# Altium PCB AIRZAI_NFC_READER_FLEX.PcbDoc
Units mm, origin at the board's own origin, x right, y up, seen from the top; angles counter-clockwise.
Board outline 158.45 x 20.7 mm, 2 copper layers (Top Layer, Bottom Layer); 35 components, 44 nets, 105 pads, 9 vias.
Unrouted connection lines stored in the file: 71.
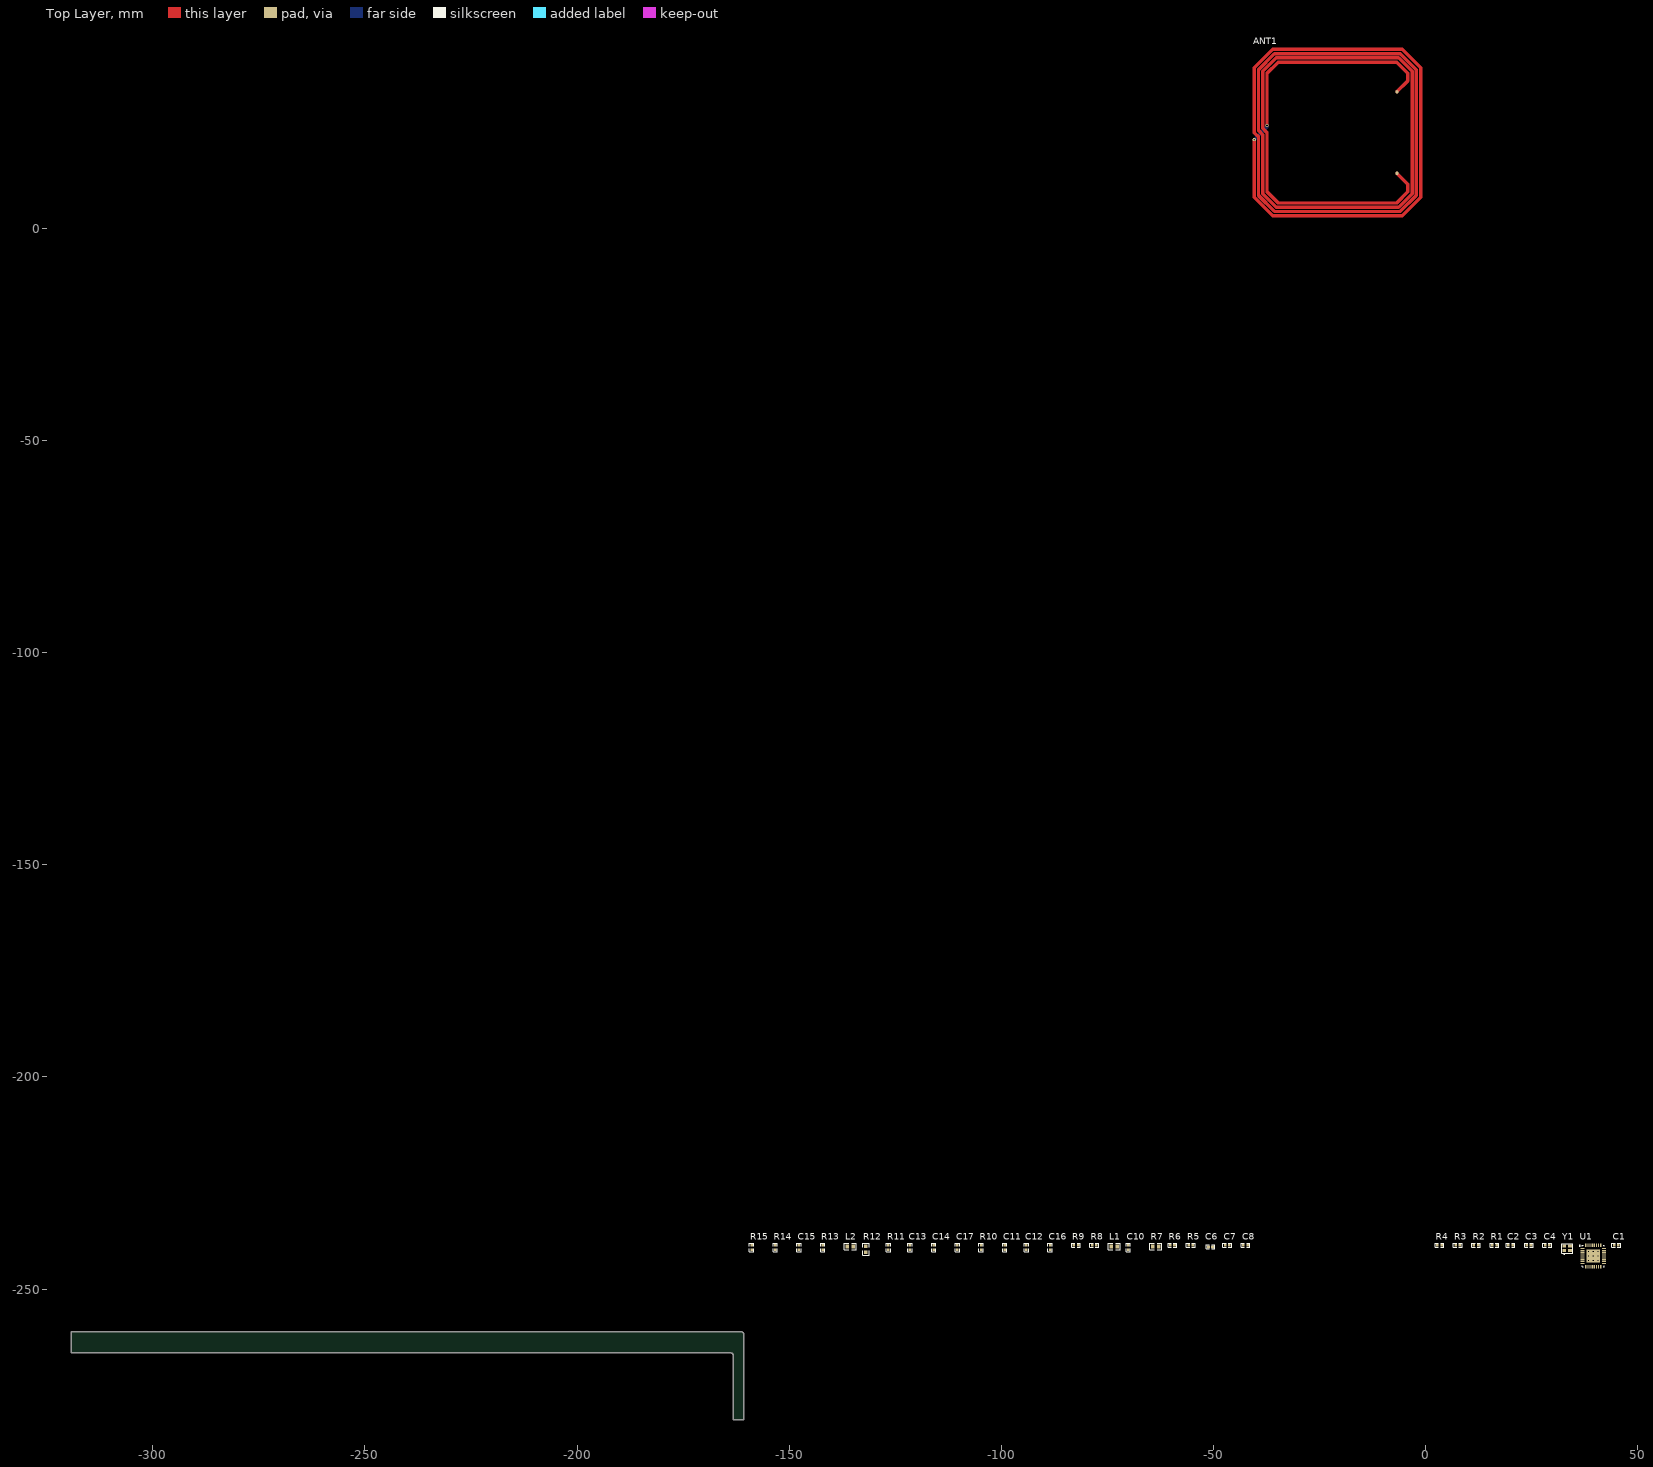
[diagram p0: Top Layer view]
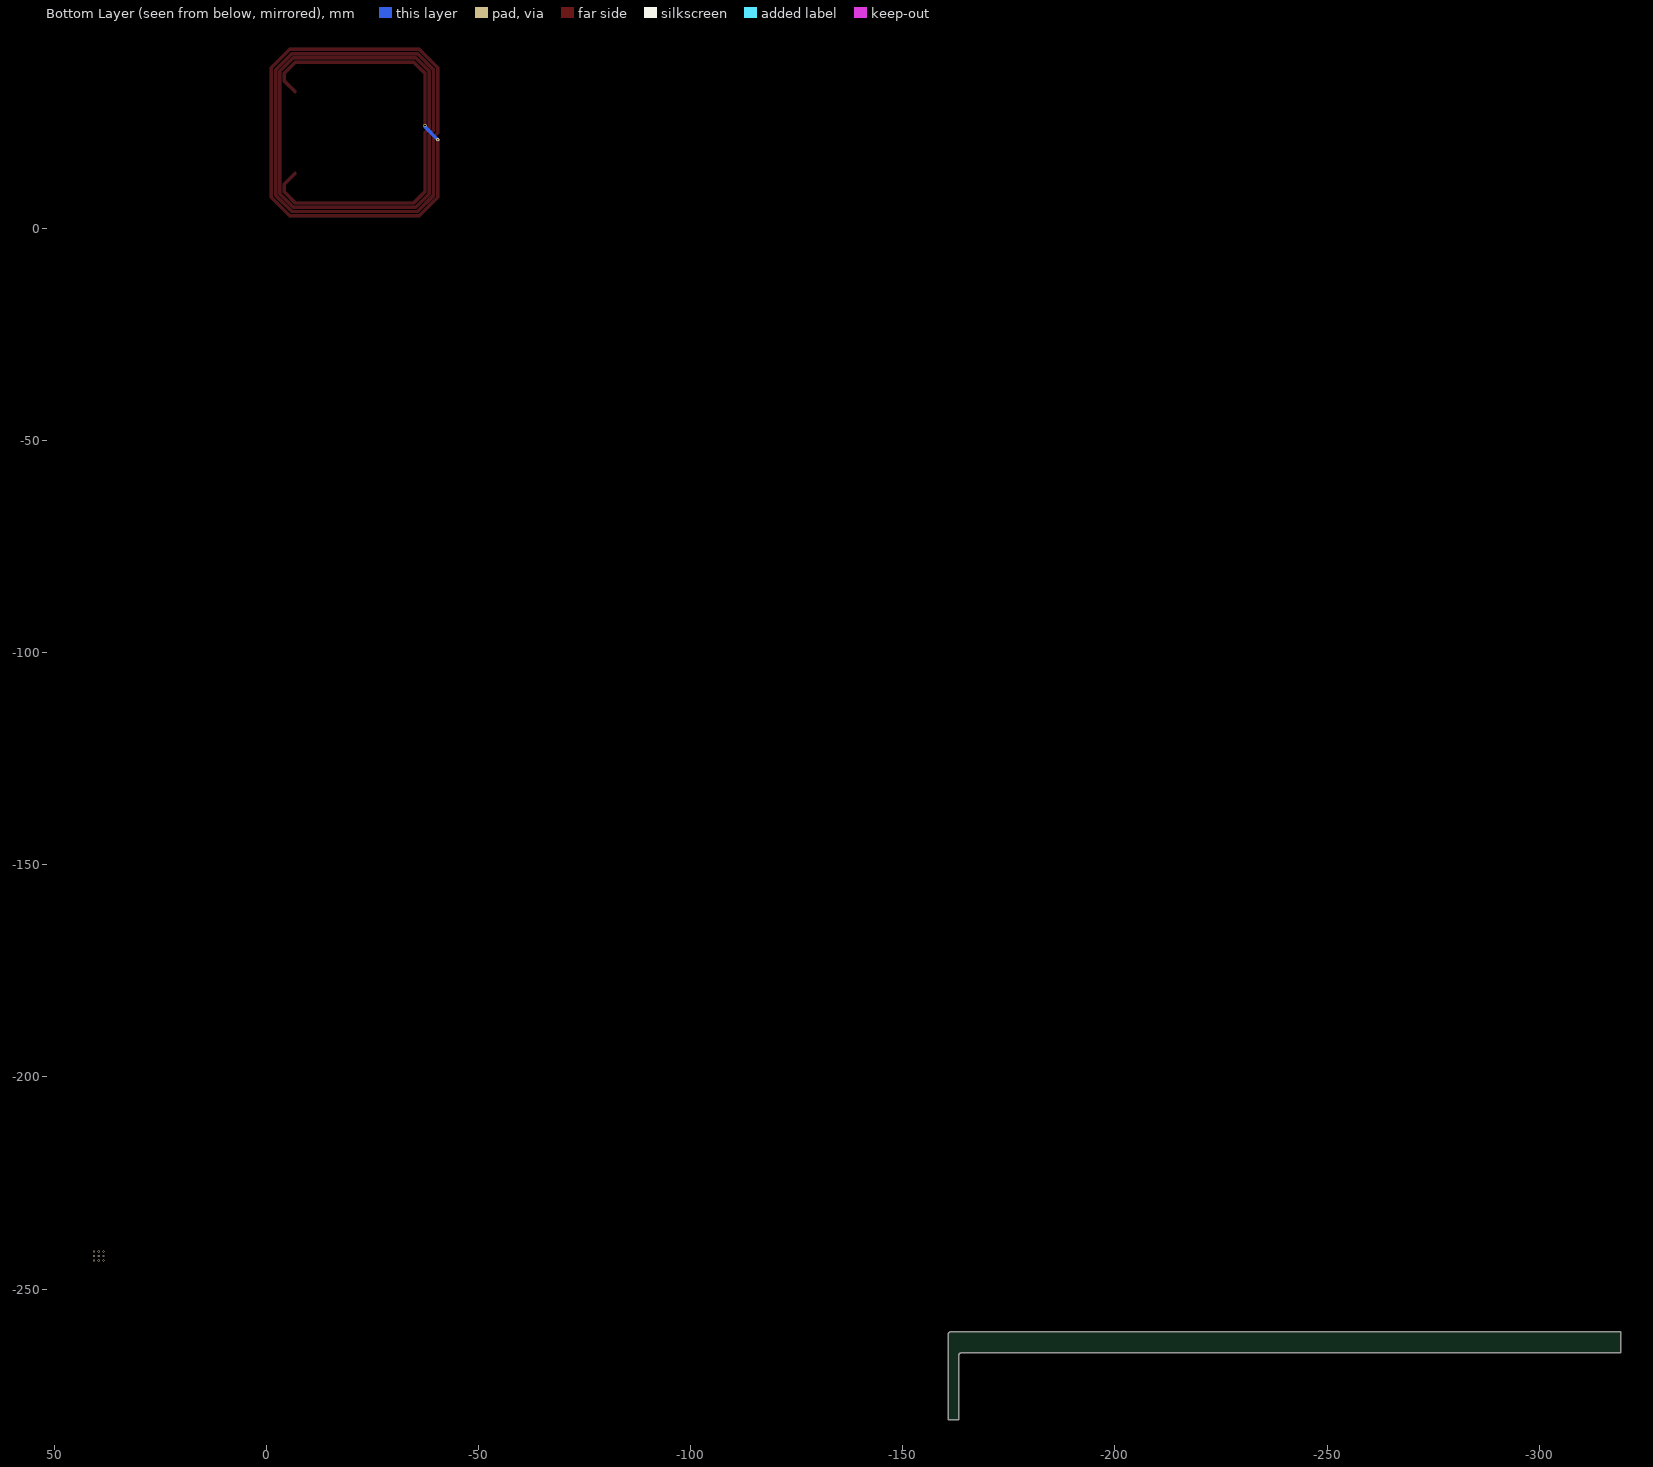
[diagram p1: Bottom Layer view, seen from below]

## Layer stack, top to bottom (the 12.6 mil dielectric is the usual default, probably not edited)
Top Solder: solder mask 0.0102, Solder Resist, Dk 3.5
Top Layer: signal copper 0.0356
Dielectric 1: dielectric 0.32, FR-4, Dk 4.8
Bottom Layer: signal copper 0.0356
Bottom Solder: solder mask 0.0102, Solder Resist, Dk 3.5

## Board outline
-319.17,-265.057 -319.17,-260.057 -161.356,-260.057 cw(c-161.356,-260.693) -160.72,-260.693 -160.72,-280.757 -163.22,-280.757 -163.22,-265.557 ccw(c-163.72,-265.557) -163.72,-265.057
board region "Layer Stack Region 1": -160.72,-274.15 -160.72,-280.757 -163.22,-280.757 -163.22,-274.15
board region "Layer Stack Region 1": -163.22,-273.337 -163.22,-265.557 -163.229,-265.459 -163.304,-265.279 -163.442,-265.141 -163.622,-265.066 -163.72,-265.057 -319.17,-265.057 -319.17,-260.057 -161.356,-260.057 -161.229,-260.057 -160.995,-260.153 -160.816,-260.332 -160.72,-260.566 -160.72,-260.693 -160.72,-273.337
board region "Layer Stack Region 2": -163.22,-274.15 -163.22,-273.337 -160.72,-273.337 -160.72,-274.15

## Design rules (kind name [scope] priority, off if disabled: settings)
Clearance Clearance_polygon_5V [OnLayer('Keep-Out Layer') vs (InNet('+5V') AND InPolygon)] p1: gap=0.254 ignorepadtopadclearanceinfootprint=FALSE
Clearance Clearance_POLYGON_KEEPOUT [(OnLayer('Keep-Out Layer')) vs (InNet('GND') AND InPolygon)] p2: gap=0.254 ignorepadtopadclearanceinfootprint=FALSE
Clearance [All] p3: gap=0.152 ignorepadtopadclearanceinfootprint=FALSE
MinimumSolderMaskSliver [All] p1: minsoldermaskwidth=0.025
PolygonConnect [All] p1: connectstyle=Direct reliefconductorwidth=0.254 reliefentries=4 polygonreliefangle="90 Angle" airgapwidth=0.254
RoomDefinition AIRZAI_NFC_READER_FLEX [InComponentClass('AIRZAI_NFC_READER_FLEX')] p1: confinementstyle=ConfineIn formatcopy=TRUE lockcomponents=FALSE outline -425.447,-395.268 -53.083,-395.268 -53.083,-151.428 -425.447,-151.428
RoutingVias [All] p1: holewidth=0.711 width=1.27 viastyle="Through Hole" minholewidth=0.203 minwidth=0.406 maxholewidth=0.711 maxwidth=1.27
SilkToSilkClearance [All] p1: silktosilkclearance=0.025
SilkToSolderMaskClearance [IsPad] p1: minsilkscreentomaskgap=0.051 clearancetoexposedcopper=TRUE
SolderMaskExpansion [All] p1: expansion=0.102
UnRoutedNet [All] p1: checkbadconnections=TRUE
Width [All] p1: maxlimit=2.54 minlimit=0.152 preferedwidth=0.254
26 further rules are at their usual default settings.

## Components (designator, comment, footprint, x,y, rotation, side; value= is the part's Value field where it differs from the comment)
ANT1 "NFC_ANT" ANTENNA-NFC-40MMX40MM -20.79,22.568 r270 top
C1 "12pF" 0402CAP 44.936,-239.693 r0 top
C2 "0.1µF" 0402CAP 20.018,-239.693 r0 top
C3 "0.1µF" 0402CAP 24.336,-239.693 r0 top
C4 "0.1µF" 0402CAP 28.654,-239.693 r0 top
C6 "1uF" CAPC0402(1005)60_M -50.721,-240.049 r0 top
C7 "0.1µF" 0402CAP -46.758,-239.693 r0 top
C8 "0.1µF" 0402CAP -42.44,-239.693 r0 top
C10 "18pF" 0402CAP -70.101,-240.201 r90 top
C11 "220pF" 0402CAP -99.184,-240.201 r90 top
C12 "47pF" 0402CAP -94.104,-240.201 r90 top
C13 "220pF" 0402CAP -121.536,-240.201 r90 top
C14 "47pF" 0402CAP -115.948,-240.201 r90 top
C15 "18pF" 0402CAP -147.698,-240.201 r90 top
C16 "DNP" 0402CAP -88.516,-240.201 r90 top
C17 "DNP" 0402CAP -110.36,-240.201 r90 top
L1 "560nH" 0603CAP -73.403,-239.947 r0 top
L2 "560mH" 0603CAP -135.633,-239.947 r0 top
R1 "0R" 0402 16.208,-239.693 r0 top
R2 "10K" 0402 11.89,-239.693 r0 top
R3 "10K" 0402 7.572,-239.693 r0 top
R4 "10K" 0402 3.254,-239.693 r0 top
R5 "1K" 0402 -55.369,-239.693 r0 top
R6 "2.7K" 0402 -59.687,-239.693 r0 top
R7 "3.3" 0603 -63.624,-239.947 r0 top
R8 "10K" 0402 -78.102,-239.693 r0 top
R9 "10K" 0402 -82.42,-239.693 r0 top
R10 "0R" 0402 -104.772,-240.201 r90 top
R11 "0R" 0402 -126.616,-240.201 r90 top
R12 "3.3" 0603 -131.95,-240.582 r90 top
R13 "10K" 0402 -142.11,-240.201 r90 top
R14 "0R" 0402 -153.286,-240.201 r90 top
R15 "0R" 0402 -158.874,-240.201 r90 top
U1 "MFRC52201HN1,157" VFQFN-32-MFRC52202HN1,157 39.5,-242.208 r0 top
Y1 "27.12MHz" XTAL_2016 33.353,-240.404 r0 top

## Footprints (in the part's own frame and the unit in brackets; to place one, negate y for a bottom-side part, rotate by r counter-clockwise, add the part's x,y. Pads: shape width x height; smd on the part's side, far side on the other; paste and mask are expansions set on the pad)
0402 [mm] "Chip Resistor, Body 1.1x0.5mm, IPC High Density"
  rect 0.6x0.6 smd: 1(-0.5,0) 2(0.5,0)
  silkscreen extent -1.02,-0.51 1.02,0.51, body extent -0.5,-0.25 0.5,0.25, height 0.27
0402CAP [mm] "Chip Capacitor, Body 1.1x0.5mm, IPC High Density"
  rect 0.6x0.6 smd: 1(-0.5,0) 2(0.5,0)
  silkscreen extent -1.02,-0.51 1.02,0.51, body extent -0.5,-0.3 0.5,0.3, height 0.19
0603 [mm] "Chip Resistor, Body 1.6x0.8mm, IPC High Density"
  rect 0.8x0.9 smd: 1(-0.7,0) 2(0.7,0)
  silkscreen extent -1.4,-0.76 1.4,0.76, body extent -0.8,-0.41 0.8,0.4, height 0.37
0603CAP [mm] "Chip Capacitor, Body 1.6x0.8mm, IPC High Density"
  rect 0.8x0.9 smd: 1(-0.7,0) 2(0.7,0)
  silkscreen extent -1.4,-0.76 1.4,0.76, body extent -0.8,-0.4 0.8,0.4, height 0.29
ANTENNA-NFC-40MMX40MM [mil] "ANTENNA-ID2+10P-01"
  round 31.5 smd: 1(-377.5,552.5) 2(377.5,552.5)
  round 30 hole 15: 1(-65,-653.54) 2(65,-771.65)
  Top Layer lines w31.5: -601.26,-771.65 -771.65,-601.26 -771.65,601.26 -601.26,771.65 601.26,771.65 771.65,601.26 771.65,-601.26 601.26,-771.65 65,-771.65 ; -601.26,-771.65 0,-771.65 39.37,-732.28 584.17,-732.28 732.28,-584.17 732.28,584.17 584.17,732.28 -584.17,732.28 -732.28,584.17 -732.28,-584.17 ; -65,-653.54 -550,-653.54 -653.54,-550 -653.54,550 -550,653.54 -478.54,653.54 -377.5,552.5 ; -732.28,-584.17 -584.17,-732.28 -19.37,-732.28 20,-692.91 567.09,-692.91 692.91,-567.09 692.91,567.09 567.09,692.91 -567.09,692.91 -692.91,567.09 -692.91,-567.09 -567.09,-692.91 -39.37,-692.91 0,-653.54 550,-653.54 653.54,-550 653.54,550 550,653.54 478.54,653.54 377.5,552.5
  Bottom Layer lines w31.5: 65,-771.65 -53.11,-653.54 -65,-653.54
CAPC0402(1005)60_M [mm] "Chip Capacitor, Body 1.0x0.5mm, Height 0.6mm, IPC Low Density"
  rect 0.72x0.72 smd: 1(-0.5,0) 2(0.5,0)
  silkscreen extent -1.02,-0.51 1.02,0.51, body extent -0.55,-0.3 0.55,0.3, height 0.6
VFQFN-32-MFRC52202HN1,157 [mm]
  rect 0.9x0.31 smd: 1(-2.529,1.75) 2(-2.529,1.25) 3(-2.529,0.75) 4(-2.529,0.25) 5(-2.529,-0.25) 6(-2.529,-0.75) 7(-2.529,-1.25) 8(-2.529,-1.75) 17(2.529,-1.75) 18(2.529,-1.25) 19(2.529,-0.75) 20(2.529,-0.25) 21(2.529,0.25) 22(2.529,0.75) 23(2.529,1.25) 24(2.529,1.75)
  rect 0.31x0.9 smd: 9(-1.75,-2.529) 10(-1.25,-2.529) 11(-0.75,-2.529) 12(-0.25,-2.529) 13(0.25,-2.529) 14(0.75,-2.529) 15(1.25,-2.529) 16(1.75,-2.529) 25(1.75,2.529) 26(1.25,2.529) 27(0.75,2.529) 28(0.25,2.529) 29(-0.25,2.529) 30(-0.75,2.529) 31(-1.25,2.529) 32(-1.75,2.529)
  rect 3.1x3.1 smd: 33(0,0)
  silkscreen extent -3.32,-2.55 2.55,2.55, body extent -2.55,-2.55 2.55,2.55, height 1
XTAL_2016 [mm] "2.00mm x 1.60mm"
  rect 0.85x0.75 smd: 1(-0.675,-0.525) 2(0.675,-0.525) 3(0.675,0.525) 4(-0.675,0.525)
  silkscreen extent -1.32,-1.47 1.32,1.14, body extent -1,-0.81 1,0.79, height 0.65

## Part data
C1: library part CAP, "CAP CER 12PF 50V C0G/NP0 0402", Case/Package=0402, Case Code (Metric)=1005, Dielectric=C0G, Dielectric Material=Ceramic, Manufacturer=KEMET, Manufacturer Part Number=C0402C120J5GACTU, Max Operating Temperature=125°C, Min Operating Temperature=-55°C, Package Quantity=1, Supplier Part Number 1=399-1013-6-ND, Temperature Coefficient=30ppm/°C, Tolerance=5%, Voltage=50V
C2 C3 C4 C7 C8: library part C0402-100n, "Capacitor, X7R, ±10%", Case-EIA=0402, Case-Metric=1005, Manufacturer=TDK, Manufacturer Part Number=C1005X7R1C104K, Rated Voltage="16 V", Supplier Part Number 1=445-4952-2-ND, Tolerance=±20%
C6: library part CAP, "CAP 1uF 16V ±10% 0402 (1005 Metric) Thickness 0.6mm SMD", Case/Package=0402, Case Code (Metric)=1005, Dielectric=X5R, Manufacturer="Taiyo Yuden", Manufacturer Part Number=EMK105BJ105KV-F, Max Operating Temperature=85°C, Min Operating Temperature=-55°C, Package Quantity=1, Supplier Part Number 1=587-2477-6-ND, Tolerance=10%, Voltage Rating=16V
C10 C15: library part 56p, "CAP CER 18PF 50V NP0 0402", Case/Package=0402, Case Code (Metric)=1005, Dielectric=C0G, Manufacturer="Kyocera AVX", Manufacturer Part Number=04025U180FAT2A, Max Operating Temperature=125°C, Min Operating Temperature=-55°C, Package Quantity=10000, Supplier Part Number 1=478-10144-1-ND, Tolerance=1%, Voltage Rating=50V
C11 C13: library part 56p, "CAP CER 220PF 50V NPO 0402", Case/Package=0402, Case Code (Metric)=1005, Dielectric=C0G, Manufacturer=Yageo, Manufacturer Part Number=CC0402FRNPO9BN221, Max Operating Temperature=125°C, Min Operating Temperature=-55°C, Supplier Part Number 1=311-3730-1-ND, Tolerance=1%, Voltage Rating=50V
C12 C14: library part 56p, "CAP CER 47PF 50V C0G/NP0 0402", Dielectric=C0G, Manufacturer=Murata, Manufacturer Part Number=GJM1555C1H470FB01D, Supplier Part Number 1=490-16376-1-ND, Tolerance=1%, Voltage Rating (DC)=50V
C16 C17: library part 56p
L1: library part Inductor, "FIXED IND 560NH 100MA 1.05 OHM", Case/Package=0603, Case Code (Metric)=1608, Current Rating=100mA, DC Resistance (DCR)=1.05R, Manufacturer=TDK, Manufacturer Part Number=MLF1608DR56JTD25, Max DC Current=30mA, Max Operating Temperature=125°C, Min Operating Temperature=-55°C, Package Quantity=4000, Ratings=AEC-Q200, Self Resonant Frequency=170MHz, Supplier Part Number 1=445-16970-1-ND, Test Frequency=25MHz, Tolerance=5%
L2: library part Inductor, "FIXED IND 560NH 100MA 1.05 OHM", Case/Package=0603, Case Code (Metric)=1608, Current Rating=100mA, DC Resistance (DCR)=1.05R, Inductance=560nH, Manufacturer=TDK, Manufacturer Part Number=MLF1608DR56JTD25, Max DC Current=30mA, Max Operating Temperature=125°C, Min Operating Temperature=-55°C, Package Quantity=4000, Ratings=AEC-Q200, Self Resonant Frequency=170MHz, Supplier Part Number 1=445-16970-1-ND, Test Frequency=25MHz, Tolerance=5%
R1 R10 R11 R14 R15: library part R0402-12k, "Resistor, ±1%, 0.063W", Case-EIA=0402, Case-Metric=1005, Manufacturer=Panasonic, Manufacturer Part Number=ERJ-2GE0R00X, Supplier Part Number 1=P0.0JTR-ND, Tolerance=±5%
R2 R3 R4 R8 R9 R13: library part R0402-12k, "Resistor 10K, ±1%, 0.063W", Case/Package=0402, Case Code (Metric)=1005, Manufacturer="Vishay Dale", Manufacturer Part Number=CRCW040210K0JNED, Max Operating Temperature=155°C, Max Power Dissipation=63mW, Min Operating Temperature=-55°C, Package Quantity=1, Resistance=10kR, Supplier Part Number 1=541-10KJDKR-ND, Temperature Coefficient=200ppm/°C, Tolerance=5%, Voltage Rating=50V
R5: library part R0402-12k, "RES SMD 1K OHM 1% 1/16W 0402", Case/Package=0402, Case Code (Metric)=1005, Manufacturer=Yageo, Manufacturer Part Number=RC0402FR-071KL, Max Operating Temperature=155°C, Min Operating Temperature=-55°C, Power Rating=62.5mW, Resistance=1kR, Supplier Part Number 1=311-1.00KLRCT-ND, Temperature Coefficient=100ppm/°C, Tolerance=1%, Voltage Rating=50V
R6: library part R0402-12k, "RES SMD 2.7K OHM 1% 1/16W 0402", Case/Package=0402, Manufacturer="Yageo Phycomp", Manufacturer Part Number=RC0402FR-072K7L, Max Operating Temperature=155°C, Min Operating Temperature=-55°C, Power Rating=63mW, Resistance=2.7kR, Supplier Part Number 1=311-2.70KLRCT-ND, Temperature Coefficient=100ppm/°C, Tolerance=1%, Voltage Rating (DC)=50V
R7 R12: library part R0402-12k, "RES SMD 3.3 OHM 1% 1/10W 0603", Case/Package=0603, Manufacturer=Yageo, Manufacturer Part Number=AC0603FR-073R3L, Max Operating Temperature=155°C, Max Power Dissipation=100mW, Min Operating Temperature=-55°C, Resistance=3.3R, Supplier Part Number 1=YAG5335CT-ND, Temperature Coefficient=200ppm/°C, Tolerance=1%
U1: "IC RFID READER 13.56MHZ 32HVQFN", Digikey Part Number=MFRC52202HN1,157-ND, Manufacturer=NXP, Mfg Package Ident=SOT617-1, Mouser Part Number=771-MFRC52202HN1157, Part Number=MFRC52202HN1,157, Temperature="-25°C to +85°C", Temperature Range High=+85°C, Temperature Range Low=-25°C
Y1: library part ZTB_2, "CRYSTAL 27.12MHZ 10PF SMD", Manufacturer="ECS International", Manufacturer Part Number=ECS-271.2-10-37-CKM-TR, Supplier Part Number 1=XC2511DKR-ND

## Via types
v1: diameter 0.5, hole 0.203, Top Layer to Bottom Layer, 9 vias

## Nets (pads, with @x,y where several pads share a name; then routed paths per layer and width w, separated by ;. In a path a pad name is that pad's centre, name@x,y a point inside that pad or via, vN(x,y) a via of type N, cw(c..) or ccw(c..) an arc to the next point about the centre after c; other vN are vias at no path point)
3V3: C2.1 C3.1 C4.1 C6.2 C7.1 R1.2 R9.2 R13.2 U1.2 U1.3 U1.12 U1.15
+5: 
ADC_CH0: 
ADC_CH1: 
EN: 
GND: C1.1 C2.2 C3.2 C4.2 C6.1 C7.2 C8.2 C11.1 C12.1 C13.2 C14.2 C16.1 C17.2 R2.1 R3.1 R4.1 R8.2 R10.2 R11.2 U1.4 U1.5 U1.10 U1.14 U1.18 U1.33 Y1.2 Y1.4
  other v1: 38.4,-243.308 39.5,-243.308 40.6,-243.308 38.4,-242.208 39.5,-242.208 40.6,-242.208 38.4,-241.108 39.5,-241.108 40.6,-241.108
INT: 
NetANT1_1: ANT1.1 R7.1
NetANT1_2: ANT1.2 R12.1
NetC1_2: C1.2 U1.21 Y1.3
NetC5_2: U1.22 Y1.1
NetC9_1: R6.2
NetC9_2: R5.2 U1.17
NetC10_1: C10.1 C12.2 C16.2 R7.2
NetC10_2: C10.2 C11.2 L1.2 R6.1
NetC13_1: C13.1 C15.2 L2.2
NetC14_1: C14.1 C15.1 C17.1 R12.2
NetL1_1: L1.1 U1.11
NetL2_1: L2.1 U1.13
NetR1_1: R1.1 U1.9
NetR2_2: R2.2 U1.28
NetR3_2: R3.2 U1.29
NetR4_2: R4.2 U1.30
NetR8_1: R8.1 U1.32
NetR9_1: R9.1 U1.1
NetR10_1: R10.1 U1.7
NetR11_1: R11.1 U1.8
NetR13_1: R13.1 U1.6
NetR14_1: R14.1 U1.31
NetR15_1: R15.1 U1.24
NetTP2_1: U1.23
PWM1: 
PWM2: 
SCL: R14.2
SDA: R15.2
SENS_I2C_SCL: 
SENS_I2C_SDA: 
SPR_GPO1: 
SPR_GPO2: 
SPR_GPO3: 
SWIPE/TO2/RDY: 
TOFINT: 
VMID: C8.1 R5.1 U1.16
XSHUNT: 
pads on no net: U1.19 U1.20 U1.25 U1.26 U1.27

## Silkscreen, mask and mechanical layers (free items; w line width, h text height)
Mechanical 1:
  drawing of 4182 lines, arcs and shapes, not listed
  text "6" at -202.432,156.213 h3.08
  text "5" at -112.432,156.213 h3.08
  text "4" at -22.432,156.213 h3.08
  text "3" at 67.568,156.213 h3.08
  text "2" at 157.568,156.213 h3.08
  text "1" at 247.568,156.213 h3.08
  text "APPD/DATE" at 285.74,147.702 h2.05
  text "ZONE" at 147.101,147.636 h2.05
  text "ECN" at 124.542,147.559 h2.05
  text "ISSUE" at 135.822,147.559 h2.05
  text "DESCRIPTION" at 198.767,147.559 h2.05
  text "DRN/DATE" at 254.828,147.559 h2.05
  text "CHK/DATE" at 270.395,147.559 h2.05
  text "NOTE: THIS DRAWING WAS PRODUCED BY COMPUTER, DO NOT UPDATE MANUALLY" at -242.391,143.775 h4
  text "E" at -250.852,113.607 h3.08
  text "E" at 297.931,113.607 h3.08
  text "9,35" at 130.353,74.586 h3.5
  text "R0,4" at -116.039,66.513 h3.5 r322.13
  text "R0,4" at -110.21,65.867 h3.5 r28.27
  text "R0,4" at -121.896,61.804 h3.5 r49.62
  text "1,9" at 163.004,57.099 h3.5 r90
  text "18,3" at 178.473,53.044 h3.5 r90
  text "R0,4" at -103.845,47.467 h3.5 r346.55
  text "R1,5" at -106.017,39.931 h3.5 r297.71
  text "5,7" at 131.444,39.183 h3.5
  text "D" at -250.852,37.607 h3.08
  text "D" at 297.931,37.607 h3.08
  text "10,6" at 21.267,33.599 h3.5
  text "42,2" at 178.451,22.795 h3.5 r90
  text "3,2" at 140.948,11.222 h3.5
  text "R1,5" at -112.196,10.296 h3.5 r52.37
  text "R1,7" at -109.771,5.551 h3.5 r19.46
  text "56" at 178.254,-26.305 h3.5 r90
  text "C" at -251.145,-38.393 h3.08
  text "C" at 297.931,-38.393 h3.08
  text "~}" at -9.206,-39.713 h3.5
  text "R1,7" at -106.648,-50.41 h3.5 r337.84
  text "R1,7" at -112.22,-50.59 h3.5 r324.73
  text "3,2" at 134.907,-53.737 h3.5
  text "R0,4" at -110.186,-57.309 h3.5 r323.84
  text "2" at 137.085,-68.3 h3.5
  text "6" at 178.201,-68.437 h3.5 r90
  text "B" at -250.852,-114.393 h3.08
  text "B" at 297.931,-114.393 h3.08
  text "Coremi Industries Co., Limited" at 182.767,-181.219 h5
  text "Airzai-041T10" at 210.409,-189.381 h3.5
  text "T10" at 279.02,-189.771 h3.5
  text "A" at -251.731,-190.393 h3.08
  text "A" at 297.931,-190.393 h3.08
  text "DRAWING NO." at 179.01,-190.756 h2.53
  text "REVISION NO." at 254.01,-190.756 h2.53
  text "Airzai" at 258.447,-194.618 h3.5
  text "TITLE:" at 179.01,-196.756 h2.53
  text "MODEL :" at 242.01,-196.756 h2.53
  text "MANIFOLD_SOLID_BREP_27740" at 193.454,-197.006 h2.5
  text "METERIAL:" at 179.01,-202.756 h2.53
  text "MASS :                 kg" at 242.01,-202.756 h2.53
  text "1" at 223.565,-207.8 h3.5
  text "P/N:" at 242.01,-208.519 h3
  text "FINISH:" at 179.01,-208.756 h2.53
  text "QTY:" at 211.51,-208.756 h2.53
  text "NOTE:" at -228.611,-210.877 h3
  text ".  TOLERANCES  ." at 210.727,-212.933 h2.02
  text "1:1" at 192.524,-213.584 h3.5
  text "1.UNSPECIFIED DRAFT ANGLE 1.0\Fgdt;{\Fgdt;~}" at -228.611,-213.907 h3
  text "SCALE:" at 179.01,-214.756 h2.53
  text "DRN.DATE" at 242.01,-214.756 h2.53
  text "Daniel Apr/20,2019" at 258.608,-215.364 h3
  text "All dimensions are in mm" at 210.565,-216.262 h1.52
  text "\Ftxt;2.UNSPECIFIED FILLET TO BE R0.3" at -228.611,-216.937 h3
  text "Daniel Apr/20,201" at 258.608,-218.394 h3
  text "unless otherwise specified." at 210.808,-219.014 h1.52
  text "A2" at -244.579,-220.635 h6
  text "PROJECTION" at 179.01,-220.756 h2.53
  text "CHK.DATE" at 242.01,-220.756 h2.53
  text "X" at 218.231,-221.462 h1.52
  text "0.20" at 228.572,-221.462 h1.52
  text ".X" at 218.231,-223.667 h1.52
  text "0.10" at 228.572,-223.667 h1.52
  text ".XX" at 218.231,-225.872 h1.52
  text "0.05" at 228.572,-225.872 h1.52
  text "1  1" at 192.164,-226.489 h3.5
  text "SHEET   OF" at 179.01,-226.756 h2.53
  text "APP.DATE" at 242.01,-226.756 h2.53
  text "ANGLE" at 217.842,-228.077 h1.52
  text "~}" at 228.572,-228.077 h1.52
  text "6" at -202.432,-233.763 h3.08
  text "5" at -112.432,-233.763 h3.08
  text "4" at -22.432,-233.763 h3.08
  text "3" at 67.568,-233.763 h3.08
  text "2" at 157.568,-233.763 h3.08
  text "1" at 247.568,-233.763 h3.08
Mechanical 2:
  lines w0.013: 199.06,-221.415 203.701,-221.415 ; 201.38,-223.735 201.38,-219.094 ; 202.664,-221.431 209.974,-221.431
Mechanical 4:
  lines w0.013: 1.115,76.77 1.115,-3.306 7.315,-54.306 7.315,-69.253 17.915,-69.253 17.915,-54.306 11.715,-3.306 11.715,76.77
